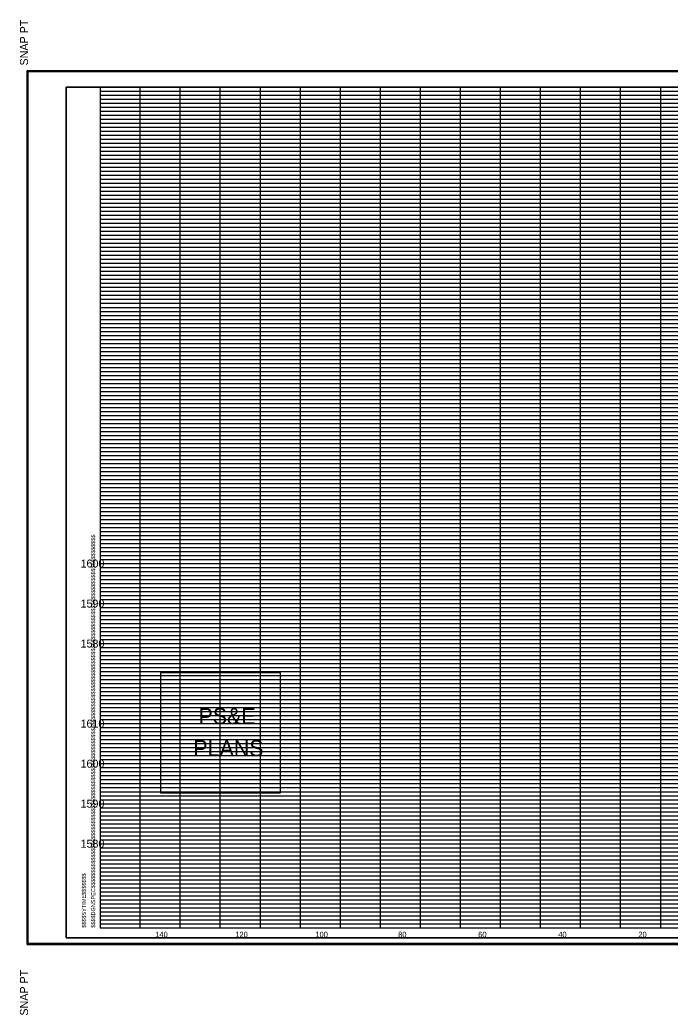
# Model space of a CAD drawing. Extents: x 980 to 1324, y 978 to 1497.
# Drawn here: x 979.9 to 1142.3, y 1248.2 to 1496.8 of the extents above; entities that cross this region are included whole.
import ezdxf

# ---------------------------------------------------------------- set-up
doc = ezdxf.new("R2010")
doc.units = 0
for name, color, linetype in [('DESIGN - SHEET - Corner Text', 7, 'Continuous'), ('DESIGN - SHEET - Light Grid', 7, 'Continuous'), ('DESIGN - SHEET - Linework', 7, 'Continuous'), ('DESIGN - SHEET - Plot Shape', 7, 'Continuous'), ('DESIGN - TYPICAL - Text', 7, 'Continuous')]:
    doc.layers.add(name, color=color, linetype=linetype)

# ---------------------------------------------------------------- blocks, each defined once
blk = doc.blocks.new('XSTSHT')
at = {"layer": 'DESIGN - SHEET - Light Grid'}
for p, q in [((0, 20.9), (8, 20.9)), ((8, 20.9), (16, 20.9)), ((0, 20.8), (8, 20.8)), ((0, 20.7), (8, 20.7)), ((8, 20.8), (16, 20.8)), ((8, 20.7), (16, 20.7)), ((0, 20.6), (8, 20.6)), ((0, 20.5), (8, 20.5)), ((0, 20.4), (8, 20.4)), ((8, 20.6), (16, 20.6)), ((8, 20.5), (16, 20.5)), ((8, 20.4), (16, 20.4)), ((0, 20.3), (8, 20.3)), ((0, 20.2), (8, 20.2)), ((8, 20.3), (16, 20.3)), ((8, 20.2), (16, 20.2)), ((0, 20.1), (8, 20.1)), ((0, 19.9), (8, 19.9)), ((8, 20.1), (16, 20.1)), ((8, 19.9), (16, 19.9)), ((0, 19.8), (8, 19.8)), ((0, 19.7), (8, 19.7)), ((8, 19.8), (16, 19.8)), ((8, 19.7), (16, 19.7)), ((0, 19.6), (8, 19.6)), ((0, 19.5), (8, 19.5)), ((0, 19.4), (8, 19.4)), ((8, 19.6), (16, 19.6)), ((8, 19.5), (16, 19.5)), ((8, 19.4), (16, 19.4)), ((0, 19.3), (8, 19.3)), ((0, 19.2), (8, 19.2)), ((8, 19.3), (16, 19.3)), ((8, 19.2), (16, 19.2)), ((0, 19.1), (8, 19.1)), ((0, 18.9), (8, 18.9)), ((8, 19.1), (16, 19.1)), ((8, 18.9), (16, 18.9)), ((0, 18.8), (8, 18.8)), ((0, 18.7), (8, 18.7)), ((8, 18.8), (16, 18.8)), ((8, 18.7), (16, 18.7)), ((0, 18.6), (8, 18.6)), ((0, 18.5), (8, 18.5)), ((0, 18.4), (8, 18.4)), ((8, 18.6), (16, 18.6)), ((8, 18.5), (16, 18.5)), ((8, 18.4), (16, 18.4)), ((0, 18.3), (8, 18.3)), ((0, 18.2), (8, 18.2)), ((8, 18.3), (16, 18.3)), ((8, 18.2), (16, 18.2)), ((0, 18.1), (8, 18.1)), ((8, 18.1), (16, 18.1)), ((0, 17.9), (8, 17.9)), ((0, 17.8), (8, 17.8)), ((0, 17.7), (8, 17.7)), ((8, 17.9), (16, 17.9)), ((8, 17.8), (16, 17.8)), ((8, 17.7), (16, 17.7)), ((0, 17.6), (8, 17.6)), ((0, 17.5), (8, 17.5)), ((8, 17.6), (16, 17.6)), ((8, 17.5), (16, 17.5)), ((0, 17.4), (8, 17.4)), ((0, 17.3), (8, 17.3)), ((0, 17.2), (8, 17.2)), ((8, 17.4), (16, 17.4)), ((8, 17.3), (16, 17.3)), ((8, 17.2), (16, 17.2)), ((0, 17.1), (8, 17.1)), ((8, 17.1), (16, 17.1)), ((0, 16.9), (8, 16.9)), ((0, 16.8), (8, 16.8)), ((0, 16.7), (8, 16.7)), ((8, 16.9), (16, 16.9)), ((8, 16.8), (16, 16.8)), ((8, 16.7), (16, 16.7)), ((0, 16.6), (8, 16.6)), ((0, 16.5), (8, 16.5)), ((8, 16.6), (16, 16.6)), ((8, 16.5), (16, 16.5)), ((0, 16.4), (8, 16.4)), ((0, 16.3), (8, 16.3)), ((0, 16.2), (8, 16.2)), ((8, 16.4), (16, 16.4)), ((8, 16.3), (16, 16.3)), ((8, 16.2), (16, 16.2)), ((0, 16.1), (8, 16.1)), ((8, 16.1), (16, 16.1)), ((0, 15.9), (8, 15.9)), ((0, 15.8), (8, 15.8)), ((0, 15.7), (8, 15.7)), ((8, 15.9), (16, 15.9)), ((8, 15.8), (16, 15.8)), ((8, 15.7), (16, 15.7)), ((0, 15.6), (8, 15.6)), ((0, 15.5), (8, 15.5)), ((8, 15.6), (16, 15.6)), ((8, 15.5), (16, 15.5)), ((0, 15.4), (8, 15.4)), ((0, 15.3), (8, 15.3)), ((0, 15.2), (8, 15.2)), ((8, 15.4), (16, 15.4)), ((8, 15.3), (16, 15.3)), ((8, 15.2), (16, 15.2)), ((0, 15.1), (8, 15.1)), ((8, 15.1), (16, 15.1)), ((0, 14.9), (8, 14.9)), ((0, 14.8), (8, 14.8)), ((0, 14.7), (8, 14.7)), ((8, 14.9), (16, 14.9)), ((8, 14.8), (16, 14.8)), ((8, 14.7), (16, 14.7)), ((0, 14.6), (8, 14.6)), ((0, 14.5), (8, 14.5)), ((8, 14.6), (16, 14.6)), ((8, 14.5), (16, 14.5)), ((0, 14.4), (8, 14.4)), ((0, 14.3), (8, 14.3)), ((0, 14.2), (8, 14.2)), ((8, 14.4), (16, 14.4)), ((8, 14.3), (16, 14.3)), ((8, 14.2), (16, 14.2)), ((0, 14.1), (8, 14.1)), ((8, 14.1), (16, 14.1)), ((0, 13.9), (8, 13.9)), ((0, 13.8), (8, 13.8)), ((0, 13.7), (8, 13.7)), ((8, 13.9), (16, 13.9)), ((8, 13.8), (16, 13.8)), ((8, 13.7), (16, 13.7)), ((0, 13.6), (8, 13.6)), ((0, 13.5), (8, 13.5)), ((8, 13.6), (16, 13.6)), ((8, 13.5), (16, 13.5)), ((0, 13.4), (8, 13.4)), ((0, 13.3), (8, 13.3)), ((0, 13.2), (8, 13.2)), ((8, 13.4), (16, 13.4)), ((8, 13.3), (16, 13.3)), ((8, 13.2), (16, 13.2)), ((0, 13.1), (8, 13.1)), ((8, 13.1), (16, 13.1)), ((0, 12.9), (8, 12.9)), ((0, 12.8), (8, 12.8)), ((0, 12.7), (8, 12.7)), ((8, 12.9), (16, 12.9)), ((8, 12.8), (16, 12.8)), ((8, 12.7), (16, 12.7)), ((0, 12.6), (8, 12.6)), ((0, 12.5), (8, 12.5)), ((8, 12.6), (16, 12.6)), ((8, 12.5), (16, 12.5)), ((0, 12.4), (8, 12.4)), ((0, 12.3), (8, 12.3)), ((0, 12.2), (8, 12.2)), ((8, 12.4), (16, 12.4)), ((8, 12.3), (16, 12.3)), ((8, 12.2), (16, 12.2)), ((0, 12.1), (8, 12.1)), ((8, 12.1), (16, 12.1)), ((0, 11.9), (8, 11.9)), ((0, 11.8), (8, 11.8)), ((0, 11.7), (8, 11.7)), ((8, 11.9), (16, 11.9)), ((8, 11.8), (16, 11.8)), ((8, 11.7), (16, 11.7)), ((0, 11.6), (8, 11.6)), ((0, 11.5), (8, 11.5)), ((8, 11.6), (16, 11.6)), ((8, 11.5), (16, 11.5)), ((0, 11.4), (8, 11.4)), ((0, 11.3), (8, 11.3)), ((0, 11.2), (8, 11.2)), ((8, 11.4), (16, 11.4)), ((8, 11.3), (16, 11.3)), ((8, 11.2), (16, 11.2)), ((0, 11.1), (8, 11.1)), ((8, 11.1), (16, 11.1)), ((0, 10.9), (8, 10.9)), ((0, 10.8), (8, 10.8)), ((0, 10.7), (8, 10.7)), ((8, 10.9), (16, 10.9)), ((8, 10.8), (16, 10.8)), ((8, 10.7), (16, 10.7)), ((0, 10.6), (8, 10.6)), ((0, 10.5), (8, 10.5)), ((8, 10.6), (16, 10.6)), ((8, 10.5), (16, 10.5)), ((0, 10.4), (8, 10.4)), ((0, 10.3), (8, 10.3)), ((0, 10.2), (8, 10.2)), ((8, 10.4), (16, 10.4)), ((8, 10.3), (16, 10.3)), ((8, 10.2), (16, 10.2)), ((0, 10.1), (8, 10.1)), ((8, 10.1), (16, 10.1)), ((0, 9.9), (8, 9.9)), ((0, 9.8), (8, 9.8)), ((0, 9.7), (8, 9.7)), ((8, 9.9), (16, 9.9)), ((8, 9.8), (16, 9.8)), ((8, 9.7), (16, 9.7)), ((0, 9.6), (8, 9.6)), ((0, 9.5), (8, 9.5)), ((8, 9.6), (16, 9.6)), ((8, 9.5), (16, 9.5)), ((0, 9.4), (8, 9.4)), ((0, 9.3), (8, 9.3)), ((0, 9.2), (8, 9.2)), ((8, 9.4), (16, 9.4)), ((8, 9.3), (16, 9.3)), ((8, 9.2), (16, 9.2)), ((0, 9.1), (8, 9.1)), ((8, 9.1), (16, 9.1)), ((0, 8.9), (8, 8.9)), ((0, 8.8), (8, 8.8)), ((8, 8.9), (16, 8.9)), ((8, 8.8), (16, 8.8)), ((0, 8.7), (8, 8.7)), ((0, 8.6), (8, 8.6)), ((0, 8.5), (8, 8.5)), ((8, 8.7), (16, 8.7)), ((8, 8.6), (16, 8.6)), ((8, 8.5), (16, 8.5)), ((0, 8.4), (8, 8.4)), ((0, 8.3), (8, 8.3)), ((8, 8.4), (16, 8.4)), ((8, 8.3), (16, 8.3)), ((0, 8.2), (8, 8.2)), ((0, 8.1), (8, 8.1)), ((8, 8.2), (16, 8.2)), ((8, 8.1), (16, 8.1)), ((0, 7.9), (8, 7.9)), ((0, 7.8), (8, 7.8)), ((8, 7.9), (16, 7.9)), ((8, 7.8), (16, 7.8)), ((0, 7.7), (8, 7.7)), ((0, 7.6), (8, 7.6)), ((0, 7.5), (8, 7.5)), ((8, 7.7), (16, 7.7)), ((8, 7.6), (16, 7.6)), ((8, 7.5), (16, 7.5)), ((0, 7.4), (8, 7.4)), ((0, 7.3), (8, 7.3)), ((8, 7.4), (16, 7.4)), ((8, 7.3), (16, 7.3)), ((0, 7.2), (8, 7.2)), ((0, 7.1), (8, 7.1)), ((8, 7.2), (16, 7.2)), ((8, 7.1), (16, 7.1)), ((0, 6.9), (8, 6.9)), ((0, 6.8), (8, 6.8)), ((8, 6.9), (16, 6.9)), ((8, 6.8), (16, 6.8)), ((0, 6.7), (8, 6.7)), ((0, 6.6), (8, 6.6)), ((0, 6.5), (8, 6.5)), ((8, 6.7), (16, 6.7)), ((8, 6.6), (16, 6.6)), ((8, 6.5), (16, 6.5)), ((0, 6.4), (8, 6.4)), ((0, 6.3), (8, 6.3)), ((8, 6.4), (16, 6.4)), ((8, 6.3), (16, 6.3)), ((0, 6.2), (8, 6.2)), ((0, 6.1), (8, 6.1)), ((8, 6.2), (16, 6.2)), ((8, 6.1), (16, 6.1)), ((0, 5.9), (8, 5.9)), ((0, 5.8), (8, 5.8)), ((8, 5.9), (16, 5.9)), ((8, 5.8), (16, 5.8)), ((0, 5.7), (8, 5.7)), ((0, 5.6), (8, 5.6)), ((0, 5.5), (8, 5.5)), ((8, 5.7), (16, 5.7)), ((8, 5.6), (16, 5.6)), ((8, 5.5), (16, 5.5)), ((0, 5.4), (8, 5.4)), ((0, 5.3), (8, 5.3)), ((8, 5.4), (16, 5.4)), ((8, 5.3), (16, 5.3)), ((0, 5.2), (8, 5.2)), ((0, 5.1), (8, 5.1)), ((8, 5.2), (16, 5.2)), ((8, 5.1), (16, 5.1)), ((0, 4.9), (8, 4.9)), ((0, 4.8), (8, 4.8)), ((8, 4.9), (16, 4.9)), ((8, 4.8), (16, 4.8)), ((0, 4.7), (8, 4.7)), ((0, 4.6), (8, 4.6)), ((0, 4.5), (8, 4.5)), ((8, 4.7), (16, 4.7)), ((8, 4.6), (16, 4.6)), ((8, 4.5), (16, 4.5)), ((0, 4.4), (8, 4.4)), ((0, 4.3), (8, 4.3)), ((8, 4.4), (16, 4.4)), ((8, 4.3), (16, 4.3)), ((0, 4.2), (8, 4.2)), ((0, 4.1), (8, 4.1)), ((8, 4.2), (16, 4.2)), ((8, 4.1), (16, 4.1)), ((0, 3.9), (8, 3.9)), ((0, 3.8), (8, 3.8)), ((8, 3.9), (16, 3.9)), ((8, 3.8), (16, 3.8)), ((0, 3.7), (8, 3.7)), ((0, 3.6), (8, 3.6)), ((0, 3.5), (8, 3.5)), ((8, 3.7), (16, 3.7)), ((8, 3.6), (16, 3.6)), ((8, 3.5), (16, 3.5)), ((0, 3.4), (8, 3.4)), ((0, 3.3), (8, 3.3)), ((8, 3.4), (16, 3.4)), ((8, 3.3), (16, 3.3)), ((0, 3.2), (8, 3.2)), ((0, 3.1), (8, 3.1)), ((8, 3.2), (16, 3.2)), ((8, 3.1), (16, 3.1)), ((0, 2.9), (8, 2.9)), ((0, 2.8), (8, 2.8)), ((8, 2.9), (16, 2.9)), ((8, 2.8), (16, 2.8)), ((0, 2.7), (8, 2.7)), ((0, 2.6), (8, 2.6)), ((0, 2.5), (8, 2.5)), ((8, 2.7), (16, 2.7)), ((8, 2.6), (16, 2.6)), ((8, 2.5), (16, 2.5)), ((0, 2.4), (8, 2.4)), ((0, 2.3), (8, 2.3)), ((8, 2.4), (16, 2.4)), ((8, 2.3), (16, 2.3)), ((0, 2.2), (8, 2.2)), ((0, 2.1), (8, 2.1)), ((8, 2.2), (16, 2.2)), ((8, 2.1), (16, 2.1)), ((0, 1.9), (8, 1.9)), ((0, 1.8), (8, 1.8)), ((8, 1.9), (16, 1.9)), ((8, 1.8), (16, 1.8)), ((0, 1.7), (8, 1.7)), ((0, 1.6), (8, 1.6)), ((0, 1.5), (8, 1.5)), ((8, 1.7), (16, 1.7)), ((8, 1.6), (16, 1.6)), ((8, 1.5), (16, 1.5)), ((0, 1.4), (8, 1.4)), ((0, 1.3), (8, 1.3)), ((8, 1.4), (16, 1.4)), ((8, 1.3), (16, 1.3)), ((0, 1.2), (8, 1.2)), ((0, 1.1), (8, 1.1)), ((8, 1.2), (16, 1.2)), ((8, 1.1), (16, 1.1)), ((0, 0.9), (8, 0.9)), ((0, 0.8), (8, 0.8)), ((8, 0.9), (16, 0.9)), ((8, 0.8), (16, 0.8)), ((0, 0.7), (8, 0.7)), ((0, 0.6), (8, 0.6)), ((0, 0.5), (8, 0.5)), ((8, 0.7), (16, 0.7)), ((8, 0.6), (16, 0.6)), ((8, 0.5), (16, 0.5)), ((0, 0.4), (8, 0.4)), ((0, 0.3), (8, 0.3)), ((8, 0.4), (16, 0.4)), ((8, 0.3), (16, 0.3)), ((0, 0.2), (8, 0.2)), ((0, 0.1), (8, 0.1)), ((8, 0.2), (16, 0.2)), ((8, 0.1), (16, 0.1))]:
    blk.add_line(p, q, dxfattribs=at)
at = {"layer": 'DESIGN - SHEET - Linework'}
for p, q in [((-1.823, -0.414), (-1.823, 21.414)), ((-1.823, 21.414), (32.217, 21.414)), ((1, 0), (1, 21)), ((2, 0), (2, 21)), ((3, 0), (3, 21)), ((4, 0), (4, 21)), ((5, 0), (5, 21)), ((6, 0), (6, 21)), ((7, 0), (7, 21)), ((8, 0), (8, 21)), ((9, 0), (9, 21)), ((10, 0), (10, 21)), ((11, 0), (11, 21)), ((12, 0), (12, 21)), ((13, 0), (13, 21)), ((14, 0), (14, 21)), ((0, 20), (28, 20)), ((0, 19), (32, 19)), ((0, 18), (32, 18)), ((0, 17), (32, 17)), ((0, 16), (32, 16)), ((0, 15), (32, 15)), ((0, 14), (32, 14)), ((0, 13), (32, 13)), ((0, 12), (32, 12)), ((0, 11), (32, 11)), ((0, 10), (32, 10)), ((0, 9), (32, 9)), ((0, 8), (32, 8)), ((0, 7), (32, 7)), ((0, 6), (32, 6)), ((0, 5), (32, 5)), ((0, 4), (32, 4)), ((0, 3), (32, 3)), ((0, 2), (32, 2)), ((0, 1), (32, 1)), ((-1.823, -0.414), (32.217, -0.414))]:
    blk.add_line(p, q, dxfattribs=at)
blk.add_lwpolyline([(0, 21), (0, 0), (32, 0), (32, 21), (0, 21)], dxfattribs=at)
at = {"layer": 'DESIGN - SHEET - Plot Shape'}
for points in [[(-1.803, 21.394), (32.197, 21.394), (32.197, -0.394), (-1.803, -0.394)], [(-0.85, 21), (32, 21), (32, -0.25), (-0.85, -0.25)]]:
    blk.add_lwpolyline(points, close=True, dxfattribs=at)
at = {"layer": 'DESIGN - SHEET - Corner Text'}
for s, height, p in [('  SNAP PT', 0.2, (-1.803, 21.394)), ('$$$$DGNSPEC$$$$$$$$$$$$$$$$$$$$$$$$$$$$$$$$$$$$$$$$$$$$$$$$$$$$$$$$$$$$$$$$$$$$$$$$$$$$$$$$$$$$$$$$$$$$$$$$$$$$$$$$$$$$$$$$$$$', 0.100002, (-0.126, 0)), ('$$$$SYTIME$$$$$$$', 0.1, (-0.358, 0)), ('SNAP PT  ', 0.2, (-1.803, -2.194))]:
    blk.add_text(s, height=height, rotation=90, dxfattribs=at).set_placement(p)

msp = doc.modelspace()

# ---------------------------------------------------------------- linework, layer by layer
at = {"layer": 'DESIGN - SHEET - Corner Text'}
msp.add_lwpolyline([(1015.02, 1333.69), (1015.02, 1303.69), (1045.02, 1303.69), (1045.02, 1333.69)], close=True, dxfattribs=at)
at = {"layer": 'DESIGN - SHEET - Plot Shape'}
msp.add_lwpolyline([(991.5, 1267.5), (1320, 1267.5), (1320, 1480), (991.5, 1480)], close=True, dxfattribs=at)

# ---------------------------------------------------------------- block references
at = {"layer": 'DESIGN - TYPICAL - Text', "xscale": 10, "yscale": 10}
msp.add_blockref('XSTSHT', (1000, 1270), dxfattribs=at)

# ---------------------------------------------------------------- texts
at = {"layer": 'DESIGN - SHEET - Corner Text'}
for s, p in [('PS&E', (1024.54, 1320.87)), ('PLANS', (1023.26, 1312.87))]:
    msp.add_text(s, height=4, dxfattribs=at).set_placement(p)
at = {"layer": 'DESIGN - TYPICAL - Text'}
for s, height, p in [('     1600     ', 2, (991.37, 1360)), ('     1590     ', 2, (991.37, 1350)), ('     1580     ', 2, (991.37, 1340)), ('     1610     ', 2, (991.37, 1320)), ('     1600     ', 2, (991.37, 1310)), ('     1590     ', 2, (991.37, 1300)), ('     1580     ', 2, (991.37, 1290)), ('     140     ', 1.4, (1011.14, 1267.6)), ('     120     ', 1.4, (1031.14, 1267.6)), ('     100     ', 1.4, (1051.14, 1267.6)), ('     80     ', 1.4, (1071.82, 1267.6)), ('     60     ', 1.4, (1091.82, 1267.6)), ('     40     ', 1.4, (1111.82, 1267.6)), ('     20     ', 1.4, (1131.82, 1267.6))]:
    msp.add_text(s, height=height, dxfattribs=at).set_placement(p)

doc.saveas('drawing.dxf')
